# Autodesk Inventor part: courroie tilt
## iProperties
Created: 2011-01
Part Number: courroie tilt
Document SubType Name: Modeling
Designer: eric
Density: 1 g/cm^3
Mass: 3.05831 g
Surface Area: 84.9437 cm^2
Volume: 3.05831 cm^3
Author: eric
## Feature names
1. Base1
